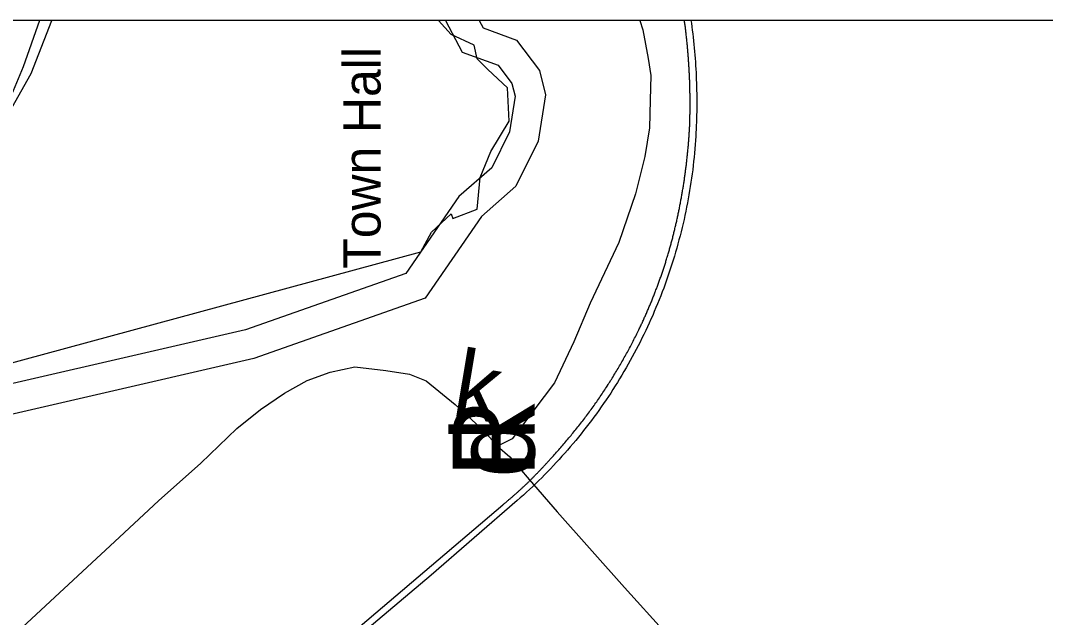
# Model space of a CAD drawing. Extents: x 1373043 to 1375788, y 550128 to 553055.
# Drawn here: x 1373435.2 to 1373506.3, y 550871.6 to 550913 of the extents above; entities that cross this region are included whole.
import ezdxf

# ---------------------------------------------------------------- set-up
doc = ezdxf.new("R2010")
doc.units = 0
for name, color, linetype in [('Old_Level_22', 7, 'Continuous'), ('Old_Level_32', 7, 'Continuous'), ('Old_Level_44', 7, 'Continuous'), ('Old_Level_50', 7, 'Continuous'), ('Old_Level_58', 7, 'Continuous'), ('Old_Level_60', 7, 'Continuous'), ('Old_Level_61', 7, 'Continuous'), ('Old_Level_9', 7, 'Continuous'), ('Prop Dimension Text', 7, 'Continuous')]:
    doc.layers.add(name, color=color, linetype=linetype)

msp = doc.modelspace()

# ---------------------------------------------------------------- linework, layer by layer
at = {"layer": 'Old_Level_32'}
for points in [[(1373478.194, 550913.044), (1373478.392, 550912.403), (1373478.763, 550910.401), (1373478.948, 550909.233), (1373478.901, 550907.516), (1373478.855, 550905.609), (1373478.531, 550903.606), (1373477.884, 550901.032), (1373476.727, 550897.646), (1373474.742, 550893.44), (1373473.612, 550890.763), (1373472.268, 550887.93), (1373469.335, 550884.041), (1373468.327, 550883.522)], [(1373421.651, 550856.004), (1373425.725, 550860.746), (1373427.403, 550862.674), (1373434.42, 550870.078), (1373442.118, 550877.225), (1373444.806, 550879.744), (1373447.738, 550882.357), (1373450.243, 550884.75), (1373451.893, 550886.072), (1373453.542, 550887.206), (1373455.131, 550888.087), (1373456.719, 550888.654), (1373458.43, 550889.032), (1373460.568, 550888.78), (1373462.218, 550888.528), (1373463.378, 550888.056), (1373465.395, 550886.419), (1373467.403, 550884.579), (1373468.327, 550883.522)], [(1373468.327, 550883.522), (1373469.182, 550882.782), (1373470.51, 550881.205), (1373472.451, 550878.972), (1373477.137, 550873.731), (1373479.973, 550870.579), (1373485.028, 550865.478), (1373486.658, 550862.574), (1373487.497, 550860.897)]]:
    msp.add_lwpolyline(points, dxfattribs=at)
at = {"layer": 'Old_Level_44'}
for points in [[(1373481.337, 550912.644), (1373481.327, 550912.715), (1373481.319, 550912.786), (1373481.309, 550912.854), (1373481.299, 550912.925), (1373481.29, 550912.996), (1373481.283, 550913.044)], [(1373481.736, 550913.044), (1373481.763, 550912.854), (1373481.797, 550912.608), (1373481.827, 550912.369), (1373481.856, 550912.124), (1373481.884, 550911.882), (1373481.911, 550911.636), (1373481.937, 550911.391), (1373481.961, 550911.148), (1373481.982, 550910.903), (1373482.005, 550910.661), (1373482.024, 550910.412), (1373482.042, 550910.167), (1373482.058, 550909.924), (1373482.073, 550909.679), (1373482.087, 550909.434), (1373482.099, 550909.188), (1373482.108, 550908.943), (1373482.116, 550908.697), (1373482.125, 550908.455), (1373482.131, 550908.206), (1373482.134, 550907.961), (1373482.139, 550907.719), (1373482.141, 550907.47), (1373482.139, 550907.224), (1373482.139, 550906.982), (1373482.134, 550906.734), (1373482.131, 550906.488), (1373482.125, 550906.246), (1373482.116, 550905.997), (1373482.107, 550905.752), (1373482.097, 550905.51), (1373482.084, 550905.264), (1373482.07, 550905.015)], [(1373481.648, 550905.723), (1373481.65, 550905.794), (1373481.653, 550905.865), (1373481.655, 550905.936), (1373481.656, 550906), (1373481.658, 550906.072), (1373481.659, 550906.143), (1373481.663, 550906.214), (1373481.664, 550906.285), (1373481.666, 550906.353), (1373481.668, 550906.424), (1373481.668, 550906.495), (1373481.671, 550906.566), (1373481.671, 550906.637), (1373481.672, 550906.701), (1373481.672, 550906.772), (1373481.674, 550906.843), (1373481.674, 550906.914), (1373481.674, 550906.982), (1373481.676, 550907.053), (1373481.676, 550907.124), (1373481.676, 550907.195), (1373481.676, 550907.266), (1373481.676, 550907.331), (1373481.676, 550907.402), (1373481.676, 550907.473), (1373481.674, 550907.544), (1373481.674, 550907.615), (1373481.674, 550907.683), (1373481.674, 550907.754), (1373481.672, 550907.825), (1373481.672, 550907.896), (1373481.671, 550907.967), (1373481.668, 550908.032), (1373481.668, 550908.103), (1373481.666, 550908.174), (1373481.664, 550908.245), (1373481.663, 550908.313), (1373481.663, 550908.384), (1373481.659, 550908.455), (1373481.658, 550908.526), (1373481.656, 550908.597), (1373481.653, 550908.662), (1373481.65, 550908.733), (1373481.648, 550908.804), (1373481.647, 550908.875), (1373481.642, 550908.943), (1373481.64, 550909.014), (1373481.637, 550909.085), (1373481.635, 550909.156), (1373481.63, 550909.227), (1373481.629, 550909.295), (1373481.624, 550909.362), (1373481.621, 550909.434), (1373481.618, 550909.505), (1373481.613, 550909.572), (1373481.611, 550909.643), (1373481.606, 550909.714), (1373481.601, 550909.786), (1373481.597, 550909.853), (1373481.593, 550909.924), (1373481.59, 550909.995), (1373481.585, 550910.063), (1373481.579, 550910.131), (1373481.576, 550910.202), (1373481.569, 550910.273), (1373481.566, 550910.344), (1373481.559, 550910.412), (1373481.556, 550910.483), (1373481.55, 550910.554), (1373481.543, 550910.625), (1373481.538, 550910.69), (1373481.534, 550910.761), (1373481.529, 550910.832), (1373481.522, 550910.903), (1373481.516, 550910.971), (1373481.509, 550911.042), (1373481.503, 550911.113), (1373481.496, 550911.181), (1373481.492, 550911.249), (1373481.485, 550911.32), (1373481.477, 550911.391), (1373481.471, 550911.458), (1373481.462, 550911.529), (1373481.458, 550911.601), (1373481.45, 550911.668), (1373481.441, 550911.739), (1373481.435, 550911.81), (1373481.429, 550911.875), (1373481.42, 550911.946), (1373481.412, 550912.017), (1373481.404, 550912.088), (1373481.396, 550912.156), (1373481.388, 550912.227), (1373481.38, 550912.298), (1373481.372, 550912.366), (1373481.362, 550912.434), (1373481.354, 550912.505), (1373481.348, 550912.573), (1373481.337, 550912.644)], [(1373480.578, 550898.411), (1373480.594, 550898.482), (1373480.612, 550898.556), (1373480.629, 550898.627), (1373480.647, 550898.702), (1373480.663, 550898.773), (1373480.679, 550898.847), (1373480.697, 550898.918), (1373480.713, 550898.992), (1373480.729, 550899.063), (1373480.747, 550899.138), (1373480.762, 550899.209), (1373480.778, 550899.283), (1373480.794, 550899.354), (1373480.81, 550899.428), (1373480.825, 550899.499), (1373480.841, 550899.577), (1373480.857, 550899.651), (1373480.873, 550899.722), (1373480.886, 550899.796), (1373480.902, 550899.868), (1373480.917, 550899.942), (1373480.931, 550900.016), (1373480.946, 550900.087), (1373480.962, 550900.161), (1373480.975, 550900.236), (1373480.989, 550900.307), (1373481.002, 550900.381), (1373481.017, 550900.452), (1373481.03, 550900.53), (1373481.044, 550900.604), (1373481.057, 550900.678), (1373481.072, 550900.749), (1373481.083, 550900.823), (1373481.098, 550900.898), (1373481.11, 550900.969), (1373481.123, 550901.043), (1373481.136, 550901.117), (1373481.148, 550901.188), (1373481.161, 550901.266), (1373481.172, 550901.34), (1373481.186, 550901.415), (1373481.198, 550901.486), (1373481.209, 550901.56), (1373481.219, 550901.634), (1373481.232, 550901.708), (1373481.243, 550901.779), (1373481.254, 550901.854), (1373481.264, 550901.931), (1373481.277, 550902.006), (1373481.288, 550902.08), (1373481.298, 550902.151), (1373481.307, 550902.225), (1373481.319, 550902.299), (1373481.33, 550902.374), (1373481.34, 550902.451), (1373481.349, 550902.522), (1373481.359, 550902.597), (1373481.369, 550902.671), (1373481.379, 550902.745), (1373481.388, 550902.819), (1373481.396, 550902.894), (1373481.406, 550902.965), (1373481.416, 550903.039), (1373481.424, 550903.116), (1373481.433, 550903.191), (1373481.441, 550903.265), (1373481.45, 550903.339), (1373481.459, 550903.414), (1373481.467, 550903.488), (1373481.475, 550903.559), (1373481.483, 550903.636), (1373481.492, 550903.711), (1373481.498, 550903.785), (1373481.504, 550903.859), (1373481.513, 550903.934), (1373481.521, 550904.008), (1373481.527, 550904.085), (1373481.534, 550904.16), (1373481.54, 550904.234), (1373481.548, 550904.305), (1373481.555, 550904.379), (1373481.559, 550904.454), (1373481.567, 550904.528), (1373481.574, 550904.602), (1373481.579, 550904.68), (1373481.585, 550904.754), (1373481.592, 550904.828), (1373481.595, 550904.902), (1373481.601, 550904.977), (1373481.606, 550905.051), (1373481.611, 550905.129), (1373481.618, 550905.203), (1373481.621, 550905.277), (1373481.627, 550905.351), (1373481.63, 550905.426), (1373481.635, 550905.497), (1373481.638, 550905.571), (1373481.645, 550905.648), (1373481.648, 550905.723)], [(1373482.07, 550905.015), (1373482.052, 550904.725), (1373482.031, 550904.437), (1373482.007, 550904.147), (1373481.981, 550903.856), (1373481.953, 550903.565), (1373481.923, 550903.271), (1373481.89, 550902.984), (1373481.855, 550902.693), (1373481.818, 550902.406), (1373481.779, 550902.115), (1373481.735, 550901.828), (1373481.692, 550901.54), (1373481.645, 550901.25), (1373481.595, 550900.962), (1373481.543, 550900.675), (1373481.492, 550900.391), (1373481.435, 550900.103), (1373481.377, 550899.816), (1373481.317, 550899.532), (1373481.254, 550899.244), (1373481.19, 550898.96), (1373481.123, 550898.679), (1373481.052, 550898.395), (1373480.981, 550898.111), (1373480.905, 550897.826), (1373480.831, 550897.549), (1373480.752, 550897.268), (1373480.671, 550896.984), (1373480.589, 550896.706), (1373480.505, 550896.425), (1373480.416, 550896.15), (1373480.327, 550895.869), (1373480.235, 550895.595), (1373480.14, 550895.32), (1373480.043, 550895.043), (1373479.945, 550894.768), (1373479.844, 550894.494), (1373479.743, 550894.219), (1373479.638, 550893.948), (1373479.53, 550893.676), (1373479.421, 550893.405), (1373479.31, 550893.137), (1373479.195, 550892.866), (1373479.081, 550892.598), (1373478.963, 550892.333), (1373478.843, 550892.068), (1373478.721, 550891.803), (1373478.596, 550891.538), (1373478.469, 550891.274), (1373478.341, 550891.012), (1373478.21, 550890.75), (1373478.08, 550890.492), (1373477.944, 550890.23), (1373477.807, 550889.975), (1373477.668, 550889.72), (1373477.527, 550889.465), (1373477.384, 550889.207), (1373477.238, 550888.955), (1373477.093, 550888.703), (1373476.943, 550888.451), (1373476.791, 550888.202), (1373476.639, 550887.95), (1373476.484, 550887.708), (1373476.327, 550887.46), (1373476.169, 550887.214), (1373476.008, 550886.972), (1373475.845, 550886.733), (1373475.682, 550886.487), (1373475.514, 550886.252), (1373475.346, 550886.009), (1373475.175, 550885.774), (1373475.003, 550885.538), (1373474.829, 550885.305), (1373474.653, 550885.07), (1373474.474, 550884.84), (1373474.294, 550884.608), (1373474.114, 550884.382), (1373473.931, 550884.156), (1373473.745, 550883.926), (1373473.558, 550883.704), (1373473.369, 550883.484), (1373473.179, 550883.261), (1373472.988, 550883.041), (1373472.793, 550882.825), (1373472.597, 550882.609), (1373472.399, 550882.392), (1373472.2, 550882.179), (1373472, 550881.966), (1373471.796, 550881.759), (1373471.591, 550881.549), (1373471.388, 550881.339), (1373471.181, 550881.136), (1373470.97, 550880.936), (1373470.76, 550880.729), (1373470.547, 550880.532), (1373470.333, 550880.332), (1373470.117, 550880.135), (1373469.901, 550879.944), (1373469.683, 550879.751)], [(1373478.125, 550891.603), (1373478.155, 550891.668), (1373478.188, 550891.732), (1373478.218, 550891.8), (1373478.251, 550891.865), (1373478.281, 550891.932), (1373478.314, 550892), (1373478.343, 550892.062), (1373478.375, 550892.129), (1373478.406, 550892.197), (1373478.435, 550892.262), (1373478.465, 550892.33), (1373478.496, 550892.398), (1373478.525, 550892.465), (1373478.556, 550892.53), (1373478.585, 550892.598), (1373478.614, 550892.666), (1373478.645, 550892.733), (1373478.674, 550892.798), (1373478.703, 550892.866), (1373478.732, 550892.934), (1373478.763, 550892.998), (1373478.79, 550893.066), (1373478.819, 550893.134), (1373478.847, 550893.202), (1373478.876, 550893.273), (1373478.905, 550893.337), (1373478.932, 550893.405), (1373478.961, 550893.473), (1373478.989, 550893.541), (1373479.016, 550893.609), (1373479.044, 550893.676), (1373479.071, 550893.744), (1373479.098, 550893.812), (1373479.124, 550893.883), (1373479.152, 550893.948), (1373479.179, 550894.016), (1373479.205, 550894.083), (1373479.232, 550894.154), (1373479.258, 550894.219), (1373479.284, 550894.287), (1373479.312, 550894.358), (1373479.337, 550894.426), (1373479.363, 550894.497), (1373479.388, 550894.561), (1373479.413, 550894.629), (1373479.439, 550894.7), (1373479.465, 550894.768), (1373479.489, 550894.839), (1373479.513, 550894.907), (1373479.539, 550894.978), (1373479.563, 550895.043), (1373479.589, 550895.114), (1373479.612, 550895.181), (1373479.636, 550895.252), (1373479.662, 550895.324), (1373479.686, 550895.391), (1373479.709, 550895.459), (1373479.733, 550895.527), (1373479.756, 550895.598), (1373479.78, 550895.666), (1373479.804, 550895.737), (1373479.825, 550895.808), (1373479.849, 550895.873), (1373479.87, 550895.944), (1373479.895, 550896.015), (1373479.916, 550896.082), (1373479.94, 550896.154), (1373479.961, 550896.225), (1373479.983, 550896.296), (1373480.004, 550896.363), (1373480.025, 550896.434), (1373480.048, 550896.506), (1373480.069, 550896.577), (1373480.092, 550896.641), (1373480.113, 550896.712), (1373480.135, 550896.783), (1373480.154, 550896.854), (1373480.176, 550896.925), (1373480.195, 550896.996), (1373480.217, 550897.064), (1373480.237, 550897.135), (1373480.256, 550897.206), (1373480.276, 550897.277), (1373480.297, 550897.345), (1373480.316, 550897.416), (1373480.335, 550897.487), (1373480.355, 550897.558), (1373480.374, 550897.629), (1373480.393, 550897.7), (1373480.411, 550897.772), (1373480.432, 550897.843), (1373480.45, 550897.914), (1373480.469, 550897.985), (1373480.487, 550898.056), (1373480.505, 550898.127), (1373480.523, 550898.198), (1373480.542, 550898.269), (1373480.56, 550898.34), (1373480.578, 550898.411)], [(1373472.05, 550882.706), (1373472.124, 550882.79), (1373472.198, 550882.867), (1373472.271, 550882.948), (1373472.344, 550883.029), (1373472.418, 550883.113), (1373472.492, 550883.19), (1373472.565, 550883.274), (1373472.636, 550883.358), (1373472.709, 550883.435), (1373472.781, 550883.519), (1373472.852, 550883.6), (1373472.923, 550883.684), (1373472.996, 550883.765), (1373473.067, 550883.849), (1373473.137, 550883.933), (1373473.206, 550884.017), (1373473.277, 550884.101), (1373473.348, 550884.185), (1373473.418, 550884.265), (1373473.485, 550884.353), (1373473.555, 550884.437), (1373473.624, 550884.524), (1373473.692, 550884.605), (1373473.762, 550884.692), (1373473.831, 550884.779), (1373473.897, 550884.86), (1373473.967, 550884.947), (1373474.033, 550885.034), (1373474.101, 550885.121), (1373474.167, 550885.209), (1373474.235, 550885.292), (1373474.299, 550885.38), (1373474.366, 550885.467), (1373474.433, 550885.554), (1373474.498, 550885.641), (1373474.563, 550885.728), (1373474.627, 550885.812), (1373474.693, 550885.903), (1373474.758, 550885.99), (1373474.821, 550886.08), (1373474.885, 550886.168), (1373474.948, 550886.258), (1373475.013, 550886.345), (1373475.076, 550886.436), (1373475.139, 550886.523), (1373475.2, 550886.613), (1373475.263, 550886.704), (1373475.326, 550886.794), (1373475.388, 550886.885), (1373475.449, 550886.972), (1373475.51, 550887.062), (1373475.573, 550887.153), (1373475.632, 550887.243), (1373475.693, 550887.337), (1373475.754, 550887.427), (1373475.812, 550887.518), (1373475.872, 550887.608), (1373475.933, 550887.699), (1373475.992, 550887.795), (1373476.051, 550887.886), (1373476.108, 550887.976), (1373476.168, 550888.07), (1373476.224, 550888.16), (1373476.284, 550888.254), (1373476.34, 550888.344), (1373476.397, 550888.441), (1373476.455, 550888.535), (1373476.512, 550888.625), (1373476.566, 550888.719), (1373476.625, 550888.813), (1373476.679, 550888.91), (1373476.734, 550889.003), (1373476.789, 550889.097), (1373476.844, 550889.194), (1373476.899, 550889.287), (1373476.952, 550889.381), (1373477.007, 550889.475), (1373477.061, 550889.572), (1373477.114, 550889.665), (1373477.167, 550889.759), (1373477.22, 550889.859), (1373477.274, 550889.953), (1373477.327, 550890.046), (1373477.379, 550890.147), (1373477.429, 550890.24), (1373477.482, 550890.334), (1373477.534, 550890.434), (1373477.582, 550890.528), (1373477.634, 550890.624), (1373477.686, 550890.725), (1373477.734, 550890.818), (1373477.784, 550890.918), (1373477.832, 550891.015), (1373477.883, 550891.109), (1373477.931, 550891.209), (1373477.981, 550891.306), (1373478.028, 550891.406), (1373478.076, 550891.503), (1373478.125, 550891.603)], [(1373468.681, 550879.45), (1373468.717, 550879.482), (1373468.756, 550879.515), (1373468.79, 550879.541), (1373468.828, 550879.573), (1373468.864, 550879.605), (1373468.901, 550879.631), (1373468.937, 550879.663), (1373468.974, 550879.696), (1373469.009, 550879.728), (1373469.045, 550879.754), (1373469.082, 550879.786), (1373469.117, 550879.818), (1373469.153, 550879.847), (1373469.19, 550879.88), (1373469.226, 550879.912), (1373469.261, 550879.938), (1373469.297, 550879.97), (1373469.332, 550880.002), (1373469.369, 550880.035), (1373469.405, 550880.064), (1373469.44, 550880.096), (1373469.476, 550880.128), (1373469.511, 550880.161), (1373469.547, 550880.19), (1373469.583, 550880.222), (1373469.618, 550880.254), (1373469.652, 550880.287), (1373469.687, 550880.316), (1373469.721, 550880.348), (1373469.757, 550880.38), (1373469.792, 550880.413), (1373469.828, 550880.442), (1373469.863, 550880.474), (1373469.897, 550880.506), (1373469.933, 550880.542), (1373469.968, 550880.574), (1373470.001, 550880.603), (1373470.036, 550880.635), (1373470.072, 550880.668), (1373470.106, 550880.703), (1373470.141, 550880.736), (1373470.175, 550880.765), (1373470.211, 550880.797), (1373470.243, 550880.832), (1373470.278, 550880.865), (1373470.312, 550880.897), (1373470.346, 550880.926), (1373470.382, 550880.962), (1373470.414, 550880.994), (1373470.448, 550881.029), (1373470.484, 550881.062), (1373470.517, 550881.094), (1373470.55, 550881.13), (1373470.584, 550881.159), (1373470.619, 550881.194), (1373470.653, 550881.226), (1373470.687, 550881.259), (1373470.719, 550881.294), (1373470.753, 550881.327), (1373470.787, 550881.362), (1373470.819, 550881.391), (1373470.853, 550881.427), (1373470.887, 550881.462), (1373470.921, 550881.494), (1373470.953, 550881.53), (1373470.986, 550881.562), (1373471.02, 550881.598), (1373471.052, 550881.627), (1373471.086, 550881.662), (1373471.12, 550881.698), (1373471.15, 550881.73), (1373471.184, 550881.766), (1373471.218, 550881.801), (1373471.249, 550881.834), (1373471.283, 550881.869), (1373471.315, 550881.905), (1373471.347, 550881.94), (1373471.381, 550881.969), (1373471.412, 550882.005), (1373471.444, 550882.04), (1373471.478, 550882.076), (1373471.509, 550882.108), (1373471.543, 550882.144), (1373471.574, 550882.179), (1373471.606, 550882.215), (1373471.64, 550882.25), (1373471.67, 550882.286), (1373471.703, 550882.321), (1373471.733, 550882.357), (1373471.766, 550882.389), (1373471.798, 550882.425), (1373471.83, 550882.46), (1373471.861, 550882.496), (1373471.893, 550882.531), (1373471.924, 550882.567), (1373471.956, 550882.602), (1373471.987, 550882.638), (1373472.019, 550882.673), (1373472.05, 550882.706)], [(1373469.683, 550879.751), (1373463.721, 550874.577), (1373452.178, 550864.84), (1373436.463, 550851.508), (1373424.554, 550841.416), (1373411.29, 550830.125), (1373406.021, 550825.713)], [(1373401.623, 550822.642), (1373406.176, 550826.404), (1373411.46, 550830.887), (1373419.143, 550837.382), (1373445.513, 550859.747), (1373468.681, 550879.45)]]:
    msp.add_lwpolyline(points, dxfattribs=at)
at = {"layer": 'Old_Level_50'}
msp.add_line((1373470.471, 550881.194), (1373470.471, 550881.194), dxfattribs=at)
at = {"layer": 'Old_Level_58'}
msp.add_lwpolyline([(1373467.051, 550913.044), (1373467.323, 550912.529), (1373469.642, 550911.687), (1373471.224, 550909.58), (1373471.645, 550907.894), (1373471.15, 550904.685), (1373469.591, 550901.548), (1373467.205, 550899.462), (1373463.295, 550893.784), (1373451.418, 550889.603), (1373428.374, 550884.29), (1373425.698, 550882.286), (1373413.931, 550876.972), (1373404.207, 550874.558), (1373403.548, 550874.147), (1373396.531, 550872.457)], dxfattribs=at)
msp.add_lwpolyline([(1373467.051, 550913.044), (1373467.323, 550912.529), (1373469.642, 550911.687), (1373471.224, 550909.58), (1373471.645, 550907.894), (1373471.15, 550904.685), (1373469.591, 550901.548), (1373467.205, 550899.462), (1373463.295, 550893.784), (1373451.418, 550889.603), (1373428.374, 550884.29), (1373425.698, 550882.286), (1373413.931, 550876.972), (1373404.207, 550874.558), (1373403.548, 550874.147), (1373396.531, 550872.457)], dxfattribs=at)
at = {"layer": 'Old_Level_60'}
for points in [[(1373436.558, 550913.044), (1373435.432, 550909.841), (1373434.167, 550906.786), (1373431.953, 550903.837), (1373429.318, 550902.151), (1373427.104, 550900.361), (1373423.731, 550897.938), (1373421.412, 550898.043), (1373417.006, 550896.047), (1373415.741, 550894.783), (1373415.741, 550894.889), (1373415.319, 550895.415), (1373414.16, 550895.415), (1373412.473, 550894.678), (1373412.052, 550893.941), (1373410.365, 550892.571), (1373408.573, 550892.15), (1373392.827, 550886.152)], [(1373424.557, 550886.573), (1373463.008, 550897.006), (1373463.745, 550898.376), (1373465.116, 550899.64), (1373465.221, 550899.324), (1373466.908, 550899.956), (1373467.119, 550902.168), (1373467.857, 550903.958), (1373469.122, 550906.065), (1373469.016, 550908.382), (1373467.646, 550909.647), (1373466.908, 550910.384), (1373466.697, 550911.332), (1373465.116, 550912.069), (1373464.229, 550913.044)]]:
    msp.add_lwpolyline(points, dxfattribs=at)
at = {"layer": 'Old_Level_61'}
for points in [[(1373464.714, 550913.044), (1373465.868, 550910.859), (1373468.358, 550909.954), (1373469.32, 550908.673), (1373469.539, 550907.798), (1373469.156, 550905.318), (1373467.922, 550902.834), (1373465.649, 550900.848), (1373461.974, 550895.51), (1373450.841, 550891.591), (1373427.484, 550886.206), (1373424.641, 550884.077), (1373413.251, 550878.933), (1373403.39, 550876.486), (1373402.738, 550876.078), (1373396.887, 550874.493)], [(1373434.437, 550906.616), (1373435.979, 550909.368), (1373437.413, 550913.044)]]:
    msp.add_lwpolyline(points, dxfattribs=at)
at = {"layer": 'Prop Dimension Text'}
msp.add_lwpolyline([(1373088.481, 550913.044), (1373088.481, 550416.544), (1373584.981, 550416.544), (1373584.981, 550913.044)], close=True, dxfattribs=at)

# ---------------------------------------------------------------- texts
at = {"layer": 'Old_Level_22'}
for s, height, rotation, p in [('Town Hall', 2.5837, 90, (1373460.213, 550895.838)), ('k', 4.651, 350.46694, (1373465.047, 550885.658))]:
    msp.add_text(s, height=height, rotation=rotation, dxfattribs=at).set_placement(p)
at = {"layer": 'Old_Level_9'}
for s, p in [('R', (1373470.893, 550881.349)), ('d', (1373470.893, 550881.32))]:
    msp.add_text(s, height=5.684, rotation=90, dxfattribs=at).set_placement(p)

doc.saveas('drawing.dxf')
